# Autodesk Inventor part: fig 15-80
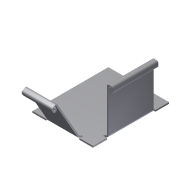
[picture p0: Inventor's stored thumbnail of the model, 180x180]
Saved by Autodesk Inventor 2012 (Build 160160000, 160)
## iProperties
Shininess: 77.0
Angle Display Precision: 2
Document Length Units: 11269
Document Angle Units: 11279
Document Time Units: 11290
Document Mass Units: 11283
Document Length Units Precision: 3
Document Angle Units Precision: 2
Compacted: True
Created: 2002-04
Part Number: fig 15-80
Document SubType Name: Sheet Metal
Density: 1 g/cm^3
Sheet Metal Rule: Default
Material: Default
Density: 0.0
Volumn: 0.0
Area: 0.0
PropertySet Name: Model Information
Control State: 0
Master: False
Checked Out: False
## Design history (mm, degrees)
node "Face1"
  sketch "Sketch1"
    geometry: L1 (-17.882, 11.882)-(2.118, 11.882); L2 (2.118, 11.882)-(2.118, -13.176); L3 (2.118, -13.176)-(-17.882, -13.176); L4 (-17.882, -13.176)-(-17.882, 11.882)
    constraints: 8 end point, 2 parallel, 1 horizontal, 1 perpendicular
    dimensions: "d17" = 20 distance of L2.end L3.end
node "Flange2"
node "Flange3"
feature "Hem8" dims "d82" = 0.5 (= BendReliefWidth), "d83" = 0.25 (= BendReliefDepth), "d84" = 1 (= MinimumRemnant), "d85" = 0.5 (= BendRadius), "d108" = 2 (= 4 x Thickness), "d109" = 0.25 (= 0.5 x Thickness), "d110" = 0.125 (= 0.5 x d109), "SeamGap" = 0.01, "Thickness" = 0.5
feature "Hem9" dims "d89" = 0.5 (= BendReliefWidth), "d90" = 0.25 (= BendReliefDepth), "d91" = 1 (= MinimumRemnant), "d92" = 0.5 (= BendRadius), "d111" = 2 (= 4 x Thickness), "d112" = 0.25 (= 0.5 x Thickness), "d113" = 0.125 (= 0.5 x d112), "SeamGap" = 0.01, "Thickness" = 0.5
body "Solid1"
face "Plate1" dims "Thickness" = 0.5
sketch "Sketch3"
  geometry: L1 (5, 0)-(20, 0); L2 (20, 0)-(20, 15); L3 (20, 15)-(5, 15); L4 (5, 15)-(5, 0)
  constraints: 8 end point
face "Plate3" dims "d6" = 15, "d7" = 90 deg, "d8" = 0.5 (= BendRadius), "d18" = 5, "d19" = 15, "Thickness" = 0.5, "MinimumRemnant" = 1 (= 2 x Thickness), "BendReliefWidth" = 0.5 (= Thickness)
bend "Bend2" dims "d6" = 15, "d7" = 90 deg, "d8" = 0.5 (= BendRadius), "d56" = 0.5 (= BendReliefWidth), "d57" = 0.25 (= BendReliefDepth), "d58" = 1 (= MinimumRemnant), "SeamGap" = 0.01, "Thickness" = 0.5, "MinimumRemnant" = 1 (= 2 x Thickness), "BendReliefWidth" = 0.5 (= Thickness), "TransitionRadius" = 0.5 (= BendRadius)
sketch "Sketch6"
  geometry: L1 (15, 0)-(5, 0); L2 (5, 0)-(5, 15); L3 (5, 15)-(15, 15); L4 (15, 15)-(15, 0)
  constraints: 8 end point
face "Plate4" dims "d20" = 5, "d21" = 10, "d23" = 15, "d24" = 60 deg, "d25" = 0.5 (= BendRadius), "Thickness" = 0.5, "MinimumRemnant" = 1 (= 2 x Thickness), "BendReliefWidth" = 0.5 (= Thickness)
bend "Bend3" dims "d22" = 0.5 (= BendRadius), "d23" = 15, "d24" = 60 deg, "d25" = 0.5 (= BendRadius), "d59" = 0.5 (= BendReliefWidth), "d60" = 0.25 (= BendReliefDepth), "d61" = 1 (= MinimumRemnant), "SeamGap" = 0.01, "Thickness" = 0.5, "MinimumRemnant" = 1 (= 2 x Thickness), "BendReliefWidth" = 0.5 (= Thickness)
sketch "Sketch12"
  geometry: L1 (0.433, 0.25)-(0, 0); L2 (-0.171, 0.046)-(-0.82, -0.329); L3 (-0.866, -0.5)-(-0.491, -1.15); L4 (-0.275, -1.025)-(-0.65, -0.375); L5 (-0.65, -0.375)-(-0.217, -0.125); L6 (-0.217, -0.125)-(0.158, -0.775); L7 (-0.924, -1.4)-(-1.299, -0.75); L8 (-1.07, 0.104)-(-0.421, 0.479); A1 r 0.125 centre (-0.108, -0.063) between (0, 0) and (-0.171, 0.046); A2 r 0.125 centre (-0.758, -0.438) between (-0.82, -0.329) and (-0.866, -0.5); A3 r 0.125 centre (-0.383, -1.087) between (-0.491, -1.15) and (-0.275, -1.025); A4 r 0.625 centre (-0.383, -1.087) between (-0.924, -1.4) and (0.158, -0.775); A5 r 0.625 centre (-0.758, -0.438) between (-1.07, 0.104) and (-1.299, -0.75); A6 r 0.625 centre (-0.108, -0.063) between (0.433, 0.25) and (-0.421, 0.479); 2 further points
  constraints: 16 end point, 12 point on circle
sketch "Sketch13"
  geometry: L1 (0.5, 0)-(0, 0); L2 (-0.125, 0.125)-(-0.875, 0.125); L3 (-1, 0)-(-1, -0.75); L4 (-0.75, -0.75)-(-0.75, 0); L5 (-0.75, 0)-(-0.25, 0); L6 (-0.25, 0)-(-0.25, -0.75); L7 (-1.5, -0.75)-(-1.5, 0); L8 (-0.875, 0.625)-(-0.125, 0.625); A1 r 0.125 centre (-0.125, 0) between (0, 0) and (-0.125, 0.125); A2 r 0.125 centre (-0.875, 0) between (-0.875, 0.125) and (-1, 0); A3 r 0.125 centre (-0.875, -0.75) between (-1, -0.75) and (-0.75, -0.75); A4 r 0.625 centre (-0.875, -0.75) between (-1.5, -0.75) and (-0.25, -0.75); A5 r 0.625 centre (-0.875, 0) between (-0.875, 0.625) and (-1.5, 0); A6 r 0.625 centre (-0.125, 0) between (0.5, 0) and (-0.125, 0.625); 2 further points
  constraints: 16 end point, 12 point on circle
other parameters: "BendRadius" = 0.5 (= Thickness), "BendReliefDepth" = 0.25 (= 0.5 x Thickness), "CornerReliefSize" = 2 (= 4 x Thickness), "d0" = 0.5 (= BendRadius), "d5" = 0.5 (= BendRadius), "d26" = 0.5 (= BendRadius), "d30" = 0.5 (= BendRadius), "JacobiRadiusSize" = 0.5 (= Thickness), "GapSize" = 0.5 (= Thickness)
